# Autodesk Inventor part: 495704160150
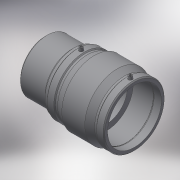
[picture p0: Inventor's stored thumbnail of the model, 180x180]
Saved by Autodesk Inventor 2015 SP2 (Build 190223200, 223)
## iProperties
Created: 2017-06
Part Number: 495704160150
Material: Generic
Description: PLASSON PE CAST IRON SPIGOT COUPLER TRANSITION 160-150
Document SubType Name: Modeling
Designer: KIM
Mass: 55.0731 g
Surface Area: 148.067 cm^2
Volume: 55.0731 cm^3
Density: 1 g/cm^3
Appearance: Default
Author: KIM
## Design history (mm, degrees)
derived "495704.ipt"
feature "Solid1::495704.ipt"
tag "TaggingFeature1"
body "Solid1"
other parameters: "d13" = 198, "d14" = 17.6296, "d15" = 97, "d16" = 97, "d17" = 152, "d19" = 3.52592, "d20" = 168 deg, "d22" = 182.36, "d23" = 194, "d24" = 176.8892, "d25" = 135 deg, "d26" = 79.2, "d27" = 135 deg, "d29" = 104, "d35" = 15, "d39" = 5 deg, "d45" = 4, "d46" = 14, "d47" = 0, "d50" = 3, "d51" = 0, "d52" = 28.13, "d53" = 7.0325, "d55" = 0.1, "d56" = 187, "d57" = 102, "d58" = 124, "d60" = 125, "d62" = 5.1, "d65" = 8.5, "L_" = 322, "L_1" = 97, "D_1" = 194, "A_" = 104, "d_2" = 12, "L_2" = 124, "H_" = 102, "d_1" = 125
